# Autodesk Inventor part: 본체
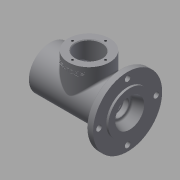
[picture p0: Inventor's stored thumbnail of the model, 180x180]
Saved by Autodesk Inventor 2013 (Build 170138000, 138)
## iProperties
Created: 2016-08
Part Number: 본체
Material: 일반
Document SubType Name: Modeling
Designer: Administrator
Density: 1 g/cm^3
Author: Administrator
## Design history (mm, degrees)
sketch "스케치1"
  geometry: L1 (-56, 0)-(-56, 31); L2 (-56, 31)-(46, 31); L3 (46, 31)-(46, 50); L4 (46, 50)-(56, 50); L5 (59, 31)-(59, 0); L6 (59, 0)-(-56, 0); L7 (56, 50)-(56, 31); L8 (56, 31)-(59, 31); 1 further point
  constraints: 16 end point, 4 perpendicular, 3 parallel, 1 point on line, 1 vertical
  dimensions: "d0" = 56 distance from line of point (0, 0) L1; "d1" = 115 distance of L5.end L1.start; "d2" = 62 diameter of L2 L6; "d3" = 100 diameter of L4 L6; "d6" = 13 distance between parallel lines of L5 L3; "d7" = 3 distance of L7.end L5.start; "d8" = 62 diameter of L8 L6
revolve "회전2" sketch "스케치1" stored, may be unused: angle "d9" = 90 deg
sketch "스케치2"
  geometry: L1 (46, -31)-(46, 31) reference; L2 (-56, -31)-(-56, 31) reference; L3 (56, -50)-(56, 50) reference; L4 (46, -50)-(46, 50) reference; L5 (59, -31)-(59, 31) reference; L6 (56, -31)-(56, 31) reference; L7 (-56, 31)-(46, 31) reference; L8 (56, 31)-(59, 31) reference; L9 (46, 50)-(56, 50) reference; L10 (-56, -31)-(46, -31) reference; L11 (-47, 0)-(59, 0); L12 (-47, 0)-(-44, 0); L13 (-44, 0)-(-44, 24); L14 (-44, 24)-(-47, 24); L15 (-47, 24)-(-47, 0); L16 (-44, 0)-(-35, 0); L17 (-35, 0)-(-35, 20); L18 (-35, 20)-(-44, 20); L19 (-44, 20)-(-44, 0); L20 (-35, 0)-(-31.75, 0); L21 (-31.75, 0)-(-31.75, 17.5); L22 (-31.75, 17.5)-(-35, 17.5); L23 (-35, 17.5)-(-35, 0); L24 (-31.75, 0)-(-30, 0); L25 (-30, 0)-(-30, 18.5); L26 (-30, 18.5)-(-31.75, 18.5); L27 (-31.75, 18.5)-(-31.75, 0); L28 (-30, 0)-(-19, 0); L29 (-19, 0)-(-19, 17.5); L30 (-19, 17.5)-(-30, 17.5); L31 (-30, 17.5)-(-30, 0); L32 (-19, 0)-(19, 0); L33 (19, 0)-(19, 26); L34 (19, 26)-(-19, 26); L35 (-19, 26)-(-19, 0); L36 (19, 0)-(30, 0); L37 (30, 0)-(30, 17.5); L38 (30, 17.5)-(19, 17.5); L39 (19, 17.5)-(19, 0); L40 (30, 0)-(35, 0); L41 (35, 0)-(35, 16.5); L42 (35, 16.5)-(30, 16.5); L43 (30, 16.5)-(30, 0); L44 (35, 0)-(37.7, 0); L45 (37.7, 0)-(37.7, 10); L46 (37.7, 10)-(35, 10); L47 (35, 10)-(35, 0); L48 (37.7, 0)-(45, 0); L49 (45, 0)-(45, 12.5); L50 (45, 12.5)-(37.7, 12.5); L51 (37.7, 12.5)-(37.7, 0); L52 (45, 12.5)-(45, 16); L53 (45, 16)-(59, 21); L54 (0, 0)-(0, -50); L55 (44.3, 12.5)-(45, 12.904); L56 (59, 0)-(59, 21); 1 further point
  constraints: 92 end point, 23 parallel, 10 horizontal, 10 perpendicular, 5 point on line, 2 midpoint, 1 collinear
  dimensions: "d10" = 14 distance from line of L5 L52.end; "d11" = 2.7 distance of L45.end L46.end; "d12" = 7.3 distance of L49.end L50.end; "d13" = 5 distance of L41.end L42.end; "d14" = 38 distance of L33.end L34.end; "d16" = 3 distance of L13.end L14.end; "d17" = 12 distance between parallel lines of L2 L19; "d18" = 21 distance between parallel lines of L17 L2; "d20" = 1.75 distance of L25.end L26.end; "d21" = 26 distance between parallel lines of L2 L31; "d23" = 42 diameter of L53.end L11; "d24" = 32 diameter of L52.end L11; "d25" = 25 diameter of L50 L11; "d26" = 20 diameter of L46 L11; "d27" = 33 diameter of L42 L11; "d28" = 35 diameter of L38 L11; "d29" = 35 diameter of L30 L11; "d30" = 52 diameter of L34 L11; "d31" = 37 diameter of L26 L11; "d32" = 35 diameter of L22 L11; "d33" = 40 diameter of L18 L11; "d34" = 48 diameter of L14 L11; "d35" = 30 deg angle of L50 L55; "d36" = 0.7 distance of L49.end L55.start
revolve "회전3" sketch "스케치2" stored, may be unused: angle "d37" = 90 deg
sketch "스케치3"
  geometry: L1 (56, -50)-(56, 50) reference; L2 (46, -50)-(46, 50) reference; L3 (59, -31)-(59, 31) reference; L4 (56, -31)-(56, 31) reference; L5 (46, -31)-(46, 31) reference; L6 (-56, -31)-(-56, 31) reference; L7 (45, 12.904)-(45, -12.904) reference; L8 (45, 12.904)-(44.3, 12.5) reference; L9 (0, 0)-(59, 0); L10 (59, 0)-(59, 21); L11 (45, 0)-(45, 16); L12 (45, 16)-(59, 21)
  constraints: 8 end point, 2 point on line, 1 midpoint, 1 parallel, 1 perpendicular
  dimensions: "d38" = 42 diameter of L10.end L9; "d40" = 32 diameter of L11.end L9; "d41" = 14 distance between parallel lines of L10 L11
revolve "회전4" sketch "스케치3" stored, may be unused: angle "d42" = 90 deg
node "작업 평면1"
sketch "스케치4"
  geometry: C1 r 30 at (0, 0); 1 further point
  constraints: 1 centre point, 1 coincident
  dimensions: "d44" = 60 diameter of C1
extrude "돌출1" join sketch "스케치4" stored distance "d45" = 10; taper "d46" = 0 deg
hole "구멍1" diameter "d49" = 38; stored, may be unused: countersink angle "d53" = 90 deg, drill point angle "d55" = 0 deg; dims "d47" = 10, "d48" = 10, "d50" = 6, "d51" = 4, "d52" = 2, "d54" = 8
hole "구멍2" diameter "d58" = 40.376; stored, may be unused: countersink angle "d62" = 90 deg, drill point angle "d64" = 0 deg; dims "d56" = 10, "d57" = 10, "d59" = 9, "d60" = 4, "d61" = 2, "d63" = 9
chamfer "모따기1" distance "d65" = 1; stored, may be unused: second distance "d66" = 2, angle "d67" = 45 deg
fillet "모깎기1" dims "d68" = 0.3
fillet "모깎기2" dims "d69" = 3
sketch "스케치5" dims "d70" = 83
  geometry: L1 (0, 0)-(0, 41.5); C1 r 31 at (0, 0) reference; C2 r 50 at (0, 0) reference; 5 further points
  constraints: 2 coincident, 2 end point, 1 vertical, 1 vertical alignment, 7 other
  dimensions: "d73" = 360 deg dimension on L1.start point (0, 41.5) (derived)
hole "구멍3" sketch "스케치5" at (0, 41.5), (-41.5, 0), (0, -41.5), (41.5, 0) diameter "d75" = 8; stored, may be unused: countersink angle "d79" = 90 deg, drill point angle "d81" = 0 deg; dims "d76" = 9, "d77" = 4, "d78" = 2, "d80" = 9
sketch "스케치6" dims "d82" = 48
  geometry: L1 (0, 0)-(0, 24); 5 further points
  constraints: 2 coincident, 2 end point, 1 vertical, 1 vertical alignment, 7 other
  dimensions: "d85" = 360 deg dimension on L1.start point (0, 24) (derived)
hole "구멍4" sketch "스케치6" at (0, 24), (-24, 0), (0, -24), (24, 0) diameter "d87" = 3.242; stored, may be unused: countersink angle "d91" = 90 deg, drill point angle "d93" = 118 deg; dims "d88" = 8, "d89" = 4, "d90" = 2, "d92" = 10
node "작업 평면2"
sketch "스케치7"
  geometry: L1 (-20.739, -6.998)-(20.739, -6.998); L2 (20.739, -6.998)-(20.739, -13.002); L3 (20.739, -13.002)-(-20.739, -13.002); L4 (-20.739, -13.002)-(-20.739, -6.998); L5 (0, -6.998)-(0, -13.002); L6 (-20.739, -10)-(20.739, -10); L7 (-30, 0)-(30, 0) reference; L8 (-56, -80)-(-56, -18) reference; 1 further point
  constraints: 4 end point, 4 midpoint, 2 other
  dimensions: "d94" = 10 distance between parallel lines of L6 L7; "d95" = 56 distance from line of L5.start L8
feature "엠보싱1" sketch "스케치7" dims "d0" = 56, "d1" = 115, "d2" = 62, "d3" = 100, "d6" = 13, "d7" = 3, "d8" = 62, "d96" = 0.5, "d97" = 0
node "솔리드2"
node "투영된 루프1"
node "투영된 루프2"
node "투영된 루프3"
node "투영된 루프4"
node "투영된 루프5"
node "투영된 루프6"
node "투영된 루프7"
other parameters: "d43" = 49
